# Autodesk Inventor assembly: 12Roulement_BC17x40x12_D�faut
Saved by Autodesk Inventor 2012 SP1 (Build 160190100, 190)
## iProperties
Created: 2011-01
Part Number: 12Roulement_BC17x40x12_D�faut
Document SubType Name: Assembly
Designer: eric
Mass: 8.37238 g
Surface Area: 70.5503 cm^2
Volume: 8.37238 cm^3
Density: 1 g/cm^3
Author: eric
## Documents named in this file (4)
- D:\Cours\Inventor salle SI\chariot_de_golf_2008\chariot_de_golf_trolem\12Roulement_BC17x40x12_Defaut.iam
- D:\Cours\Inventor salle SI\chariot_de_golf_2008\chariot_de_golf_trolem\Roulement_r1rb_Eroul40_Defaut.ipt
- D:\Cours\Inventor salle SI\chariot_de_golf_2008\chariot_de_golf_trolem\Roulement_r1rb_Bext40_Defaut.ipt
- D:\Cours\Inventor salle SI\chariot_de_golf_2008\chariot_de_golf_trolem\Roulement_r1rb_Bint40_Defaut.ipt
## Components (12 placed, 3 different names)
1. Roulement_r1rb_Eroul40_Defaut:1
2. Roulement_r1rb_Eroul40_Defaut:2
3. Roulement_r1rb_Eroul40_Defaut:3
4. Roulement_r1rb_Bext40_Defaut:1
5. Roulement_r1rb_Eroul40_Defaut:4
6. Roulement_r1rb_Eroul40_Defaut:5
7. Roulement_r1rb_Eroul40_Defaut:6
8. Roulement_r1rb_Eroul40_Defaut:7
9. Roulement_r1rb_Bint40_Defaut:1
10. Roulement_r1rb_Eroul40_Defaut:8
11. Roulement_r1rb_Eroul40_Defaut:9
12. Roulement_r1rb_Eroul40_Defaut:10
